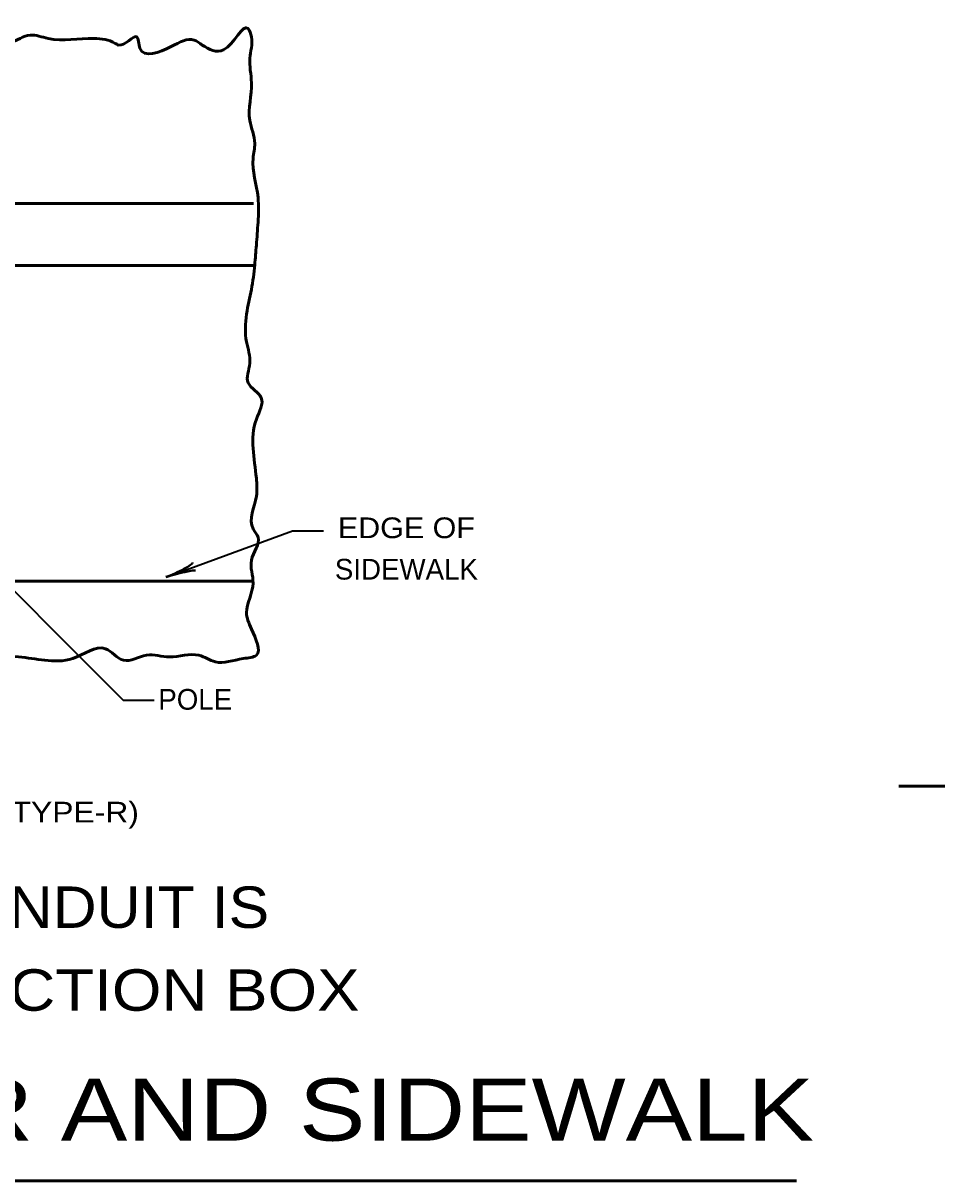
# Model space of a CAD drawing. Extents: x -90 to 623, y -379 to 75.
# Drawn here: x 119.8 to 208.1, y -256.7 to -144.9 of the extents above; entities that cross this region are included whole.
import ezdxf
from ezdxf.enums import TextEntityAlignment as Align

# ---------------------------------------------------------------- set-up
doc = ezdxf.new("R2010")
doc.units = 0
doc.header["$LTSCALE"] = 0.8
doc.layers.add('1', color=7, linetype='Continuous', lineweight=35)

msp = doc.modelspace()

# ---------------------------------------------------------------- linework, layer by layer
at = {"layer": '1', "lineweight": 53}
for p, q in [((42.0595, -162.3067), (142.0595, -162.3067)), ((42.0595, -168.3067), (142.0595, -168.3067)), ((42.3769, -198.8067), (142.0708, -198.8067)), ((204.4208, -218.5891), (370.8755, -218.5891)), ((-3.2295, -256.7077), (194.5145, -256.7077))]:
    msp.add_line(p, q, dxfattribs=at)
at = {"layer": '1'}
for points in [[(113.0107, -193.8116), (129.4815, -210.2824), (132.4815, -210.2824)], [(133.6284, -198.3907), (145.8444, -193.9445), (148.8444, -193.9445)]]:
    msp.add_lwpolyline(points, dxfattribs=at)
at = {"layer": '1', "lineweight": 40}
for centre, major_axis, ratio, start_param, end_param in [((134.5593, -197.7579), (-1.6246, -0.7575), 0.122415, 0.89635335, 3.14159265), ((134.7537, -198.2064), (1.7106, 0.4357), 0.07063, 6.28230741, 8.55970261)]:
    msp.add_ellipse(centre, major_axis=major_axis, ratio=ratio, start_param=start_param, end_param=end_param, dxfattribs=at)
at = {"layer": '1', "lineweight": 53}
msp.add_spline([(105.117, -146.5359), (106.7013, -146.8528), (109.3948, -147.0112), (110.9792, -146.8528), (111.9297, -147.0112), (115.4153, -147.3282), (118.5841, -146.8528), (120.4853, -146.0607), (122.2281, -146.3775), (126.6643, -146.3775), (128.724, -146.8528), (129.0408, -147.0112), (130.7837, -146.2191), (131.1005, -147.3282), (134.1108, -147.1697), (136.3289, -146.5359), (137.1211, -147.0112), (139.1807, -147.4866), (141.5573, -145.4269), (141.8742, -146.2191), (141.7157, -148.2788), (141.8742, -150.6553), (141.7157, -154.2993), (142.1911, -156.5174), (142.0327, -157.9433), (142.5079, -161.7458), (142.5079, -164.1223), (142.3495, -166.3405), (142.1911, -168.2417), (141.8742, -170.6182), (141.3989, -172.9948), (141.3989, -175.6882), (141.7157, -177.7479), (141.5573, -179.6491), (142.8248, -181.075), (142.3495, -183.1347), (142.0327, -185.9866), (142.3495, -188.8384), (142.3495, -190.5812), (142.0327, -193.7499), (142.5079, -194.5421), (141.8742, -196.7602), (142.0327, -198.9783), (141.3989, -201.8302), (141.8742, -203.4145), (142.3495, -205.9495), (141.082, -206.2664), (138.3886, -206.5832), (136.8042, -205.9495), (133.9524, -206.1079), (131.7343, -205.9495), (129.5162, -206.4248), (127.7733, -205.3157), (124.6047, -206.2664), (121.9112, -206.4248), (119.3762, -206.1079), (116.2075, -206.2664), (111.6129, -206.5832), (110.8207, -205.6327), (103.8495, -205.9495), (99.8886, -206.4248), (96.403, -207.0586), (94.9771, -205.7911), (90.6993, -206.1079), (88.0059, -205.3157), (83.5697, -206.5832), (80.0841, -205.9495), (75.331, -206.7417), (71.5285, -206.1079), (67.4092, -206.5832), (62.973, -205.7911), (59.9627, -206.4248), (56.9524, -206.7417), (53.6253, -205.9495), (49.9812, -206.5832), (48.5553, -206.2664), (46.3372, -206.4248), (42.6932, -206.9002), (42.3762, -204.5236), (42.2178, -201.3548), (42.3762, -198.8199), (42.5347, -195.6512), (41.901, -190.1059), (42.6932, -187.8877), (42.3762, -183.4516), (42.6932, -181.2335), (42.6932, -179.4907), (42.0594, -176.3219), (42.2178, -173.787), (42.8516, -171.5688), (42.2178, -169.0339), (41.7425, -164.5977), (42.6932, -160.6368), (42.2178, -157.1512), (41.5841, -153.1902), (42.0594, -148.4372), (42.0595, -146.3067)], degree=3, dxfattribs=at)

# ---------------------------------------------------------------- texts
at = {"layer": '1'}
for s, height, width, p in [('EDGE OF', 2, 1.1, (156.8412, -194.6384)), ('WHEN UNDERGROUND CONDUIT IS', 4, 1.1, (92.4321, -232.2779)), ("GREATER THAN 10' USE JUNCTION BOX", 4, 1.15, (92.4321, -240.2779))]:
    msp.add_text(s, height=height, dxfattribs=dict(at, width=width)).set_placement(p, align=Align.CENTER)
msp.add_text('SIDEWALK', height=2, dxfattribs=at).set_placement((156.8411, -198.6384), align=Align.CENTER)
msp.add_text('POLE', height=2, dxfattribs=at).set_placement((132.8758, -211.2059))
for s, height, width, p in [('CONDUIT (TYPE-R)', 2, 1.15, (102.8104, -222.0992)), ('TYPICAL PLAN IN GUTTER AND SIDEWALK', 6, 1.2, (-1.7292, -252.8244))]:
    msp.add_text(s, height=height, dxfattribs=dict(at, width=width)).set_placement(p)

doc.saveas('drawing.dxf')
